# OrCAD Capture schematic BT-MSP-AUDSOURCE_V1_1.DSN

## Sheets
1 PAGE2 - MSP430: size B; title: BT-MSP-AUDSOURCE; rev: 1.1
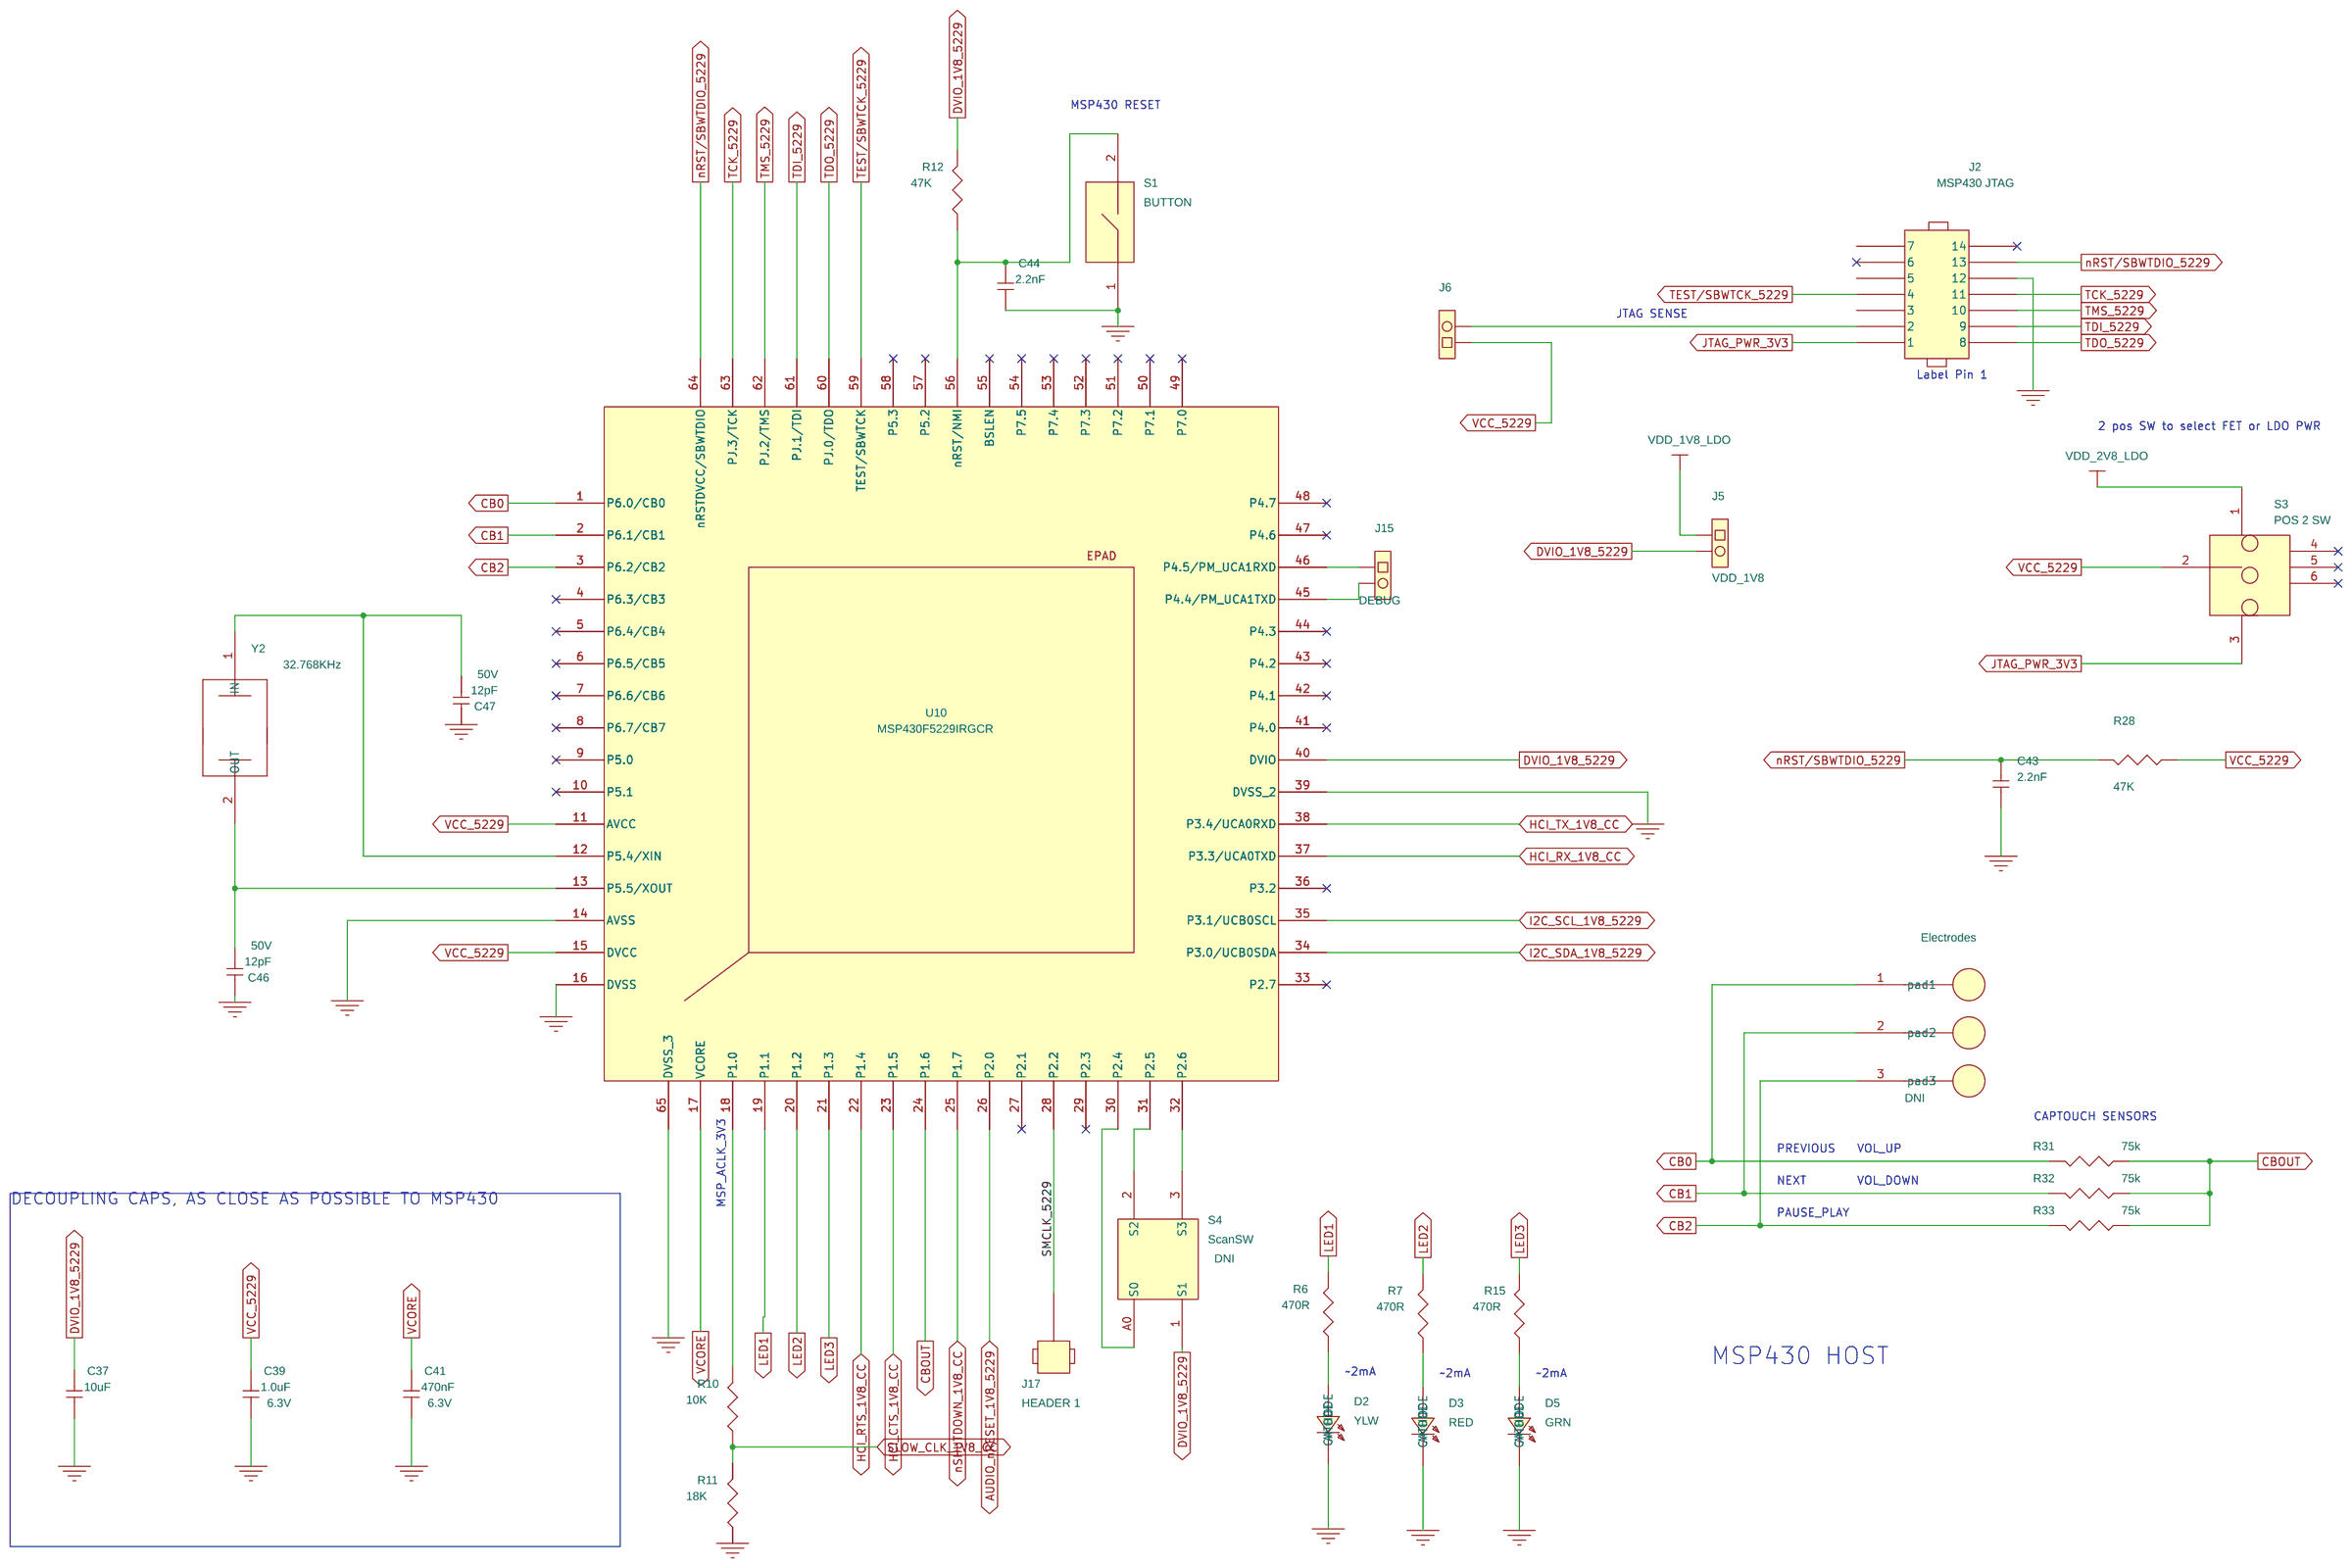
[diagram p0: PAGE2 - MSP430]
2 PAGE3 - CC256x QFN: size B
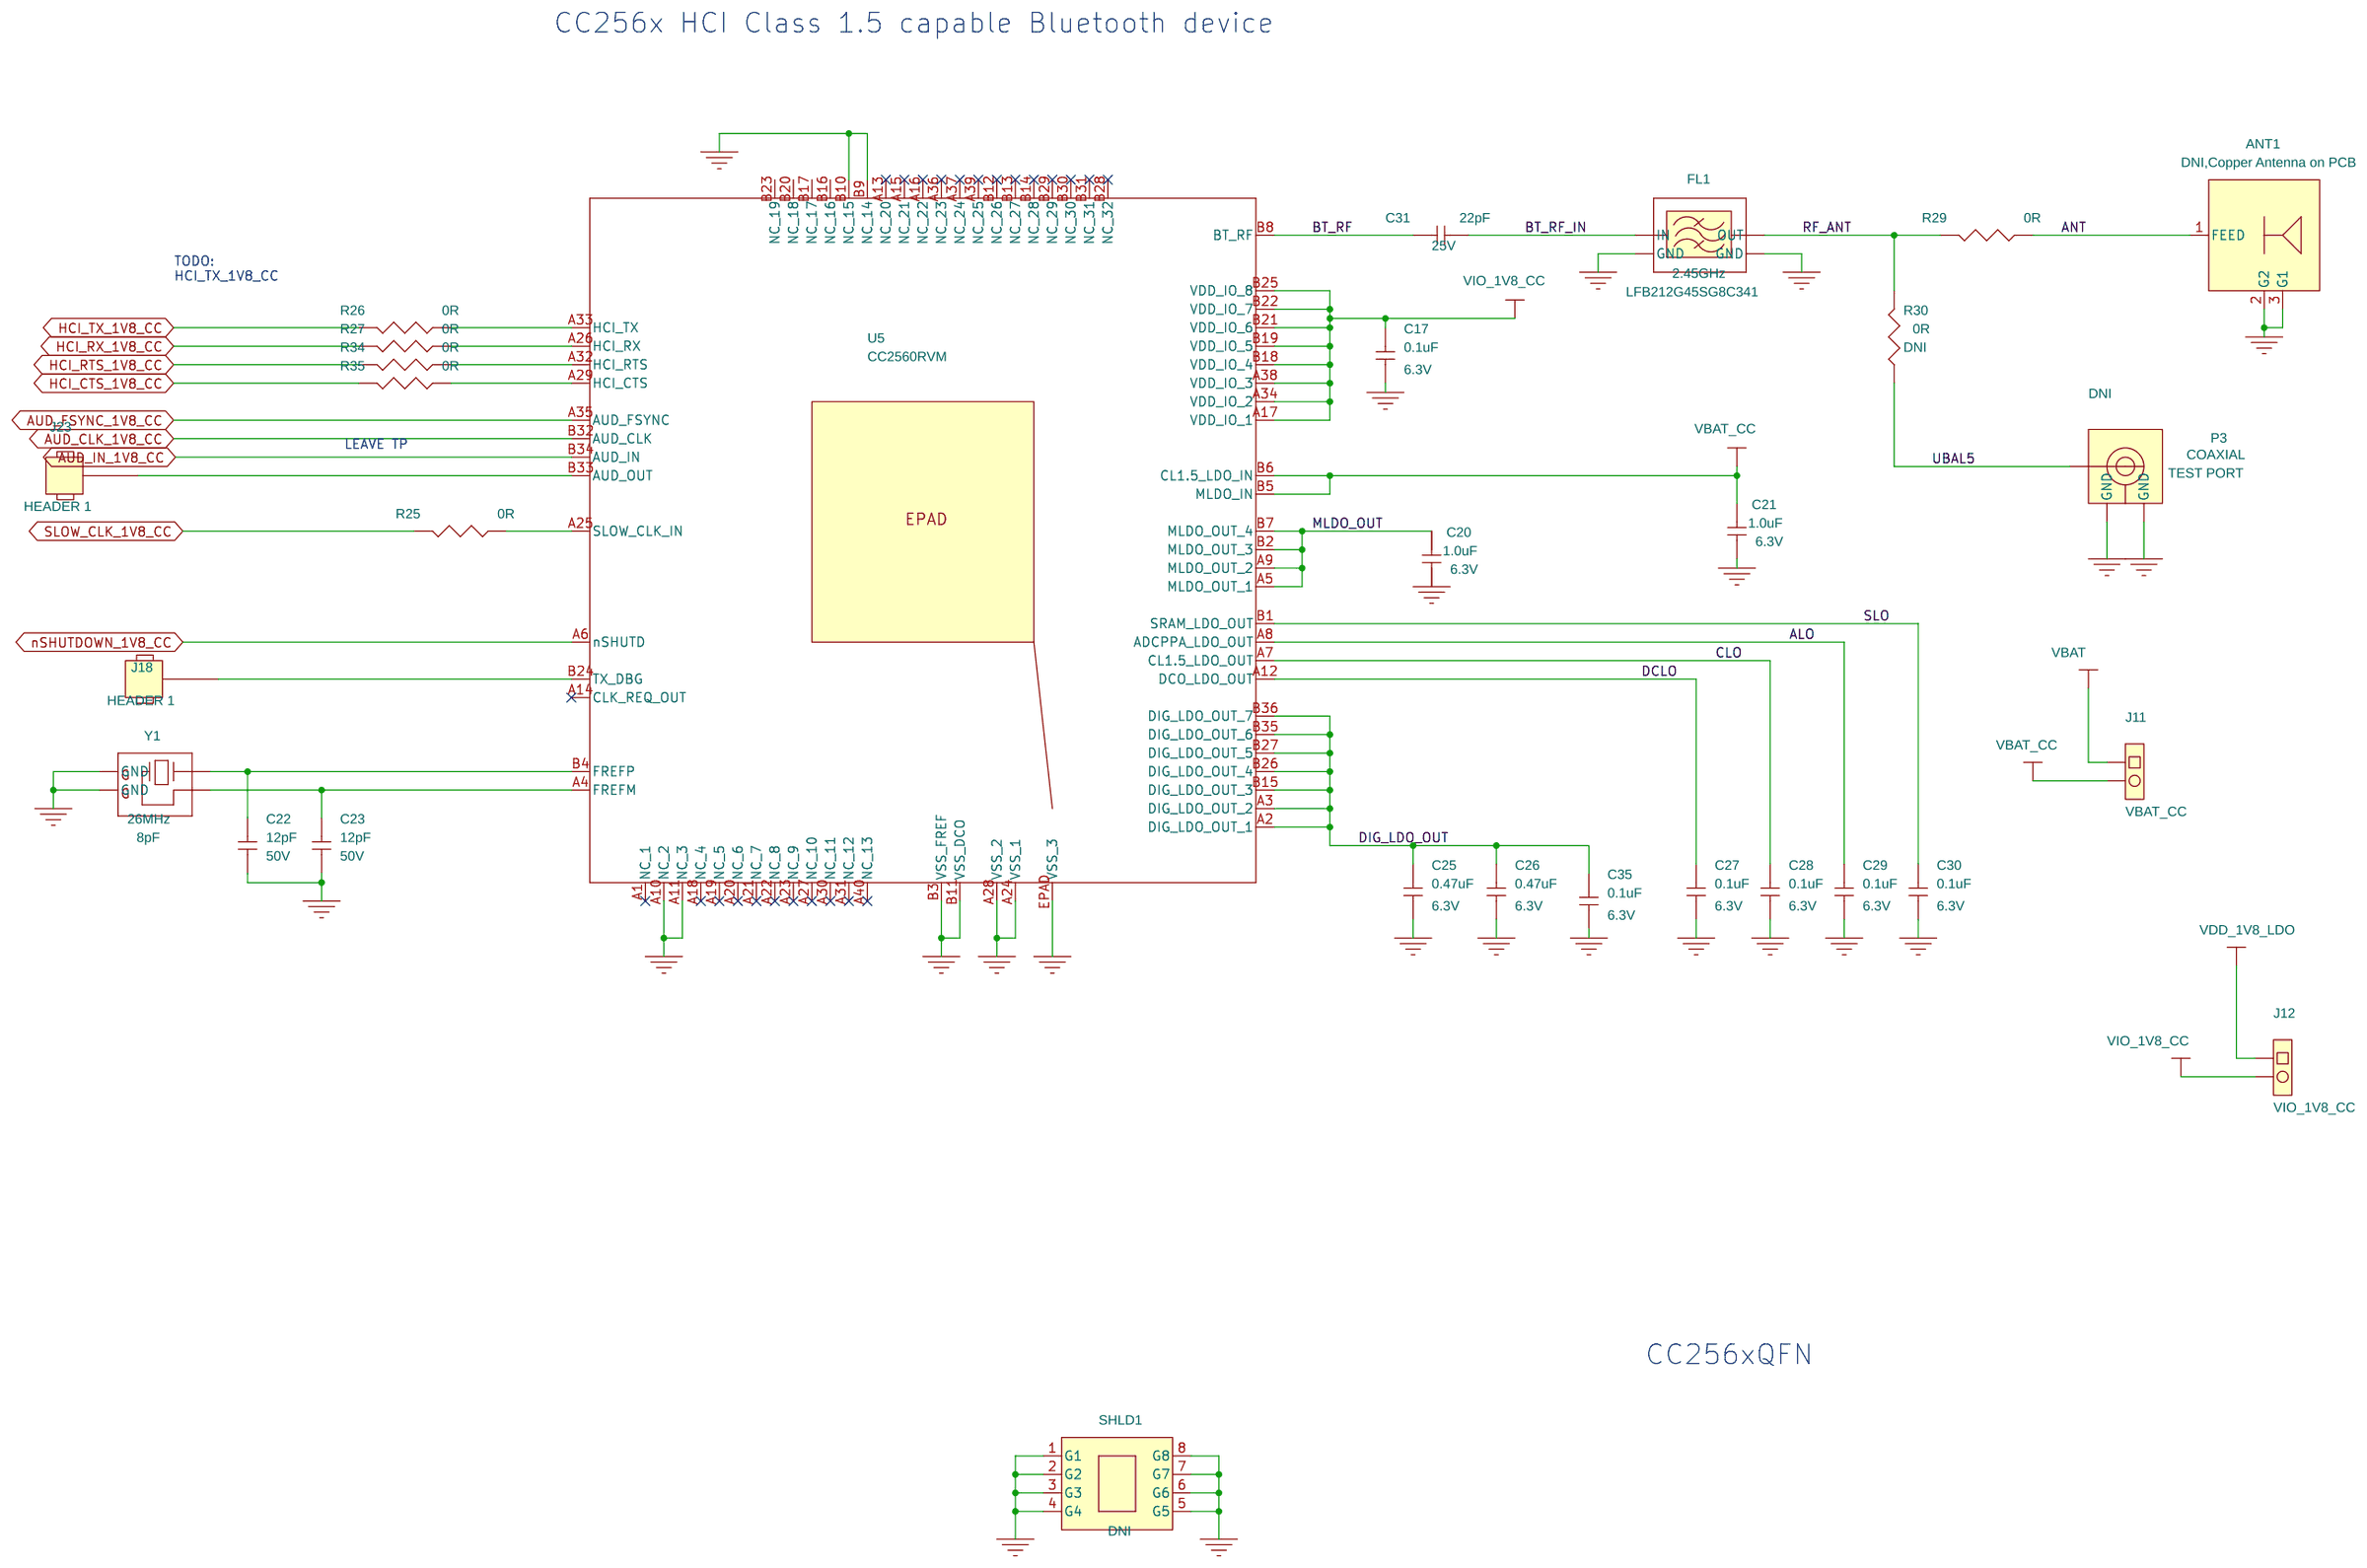
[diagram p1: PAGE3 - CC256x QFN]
3 PAGE4 - Power: size B
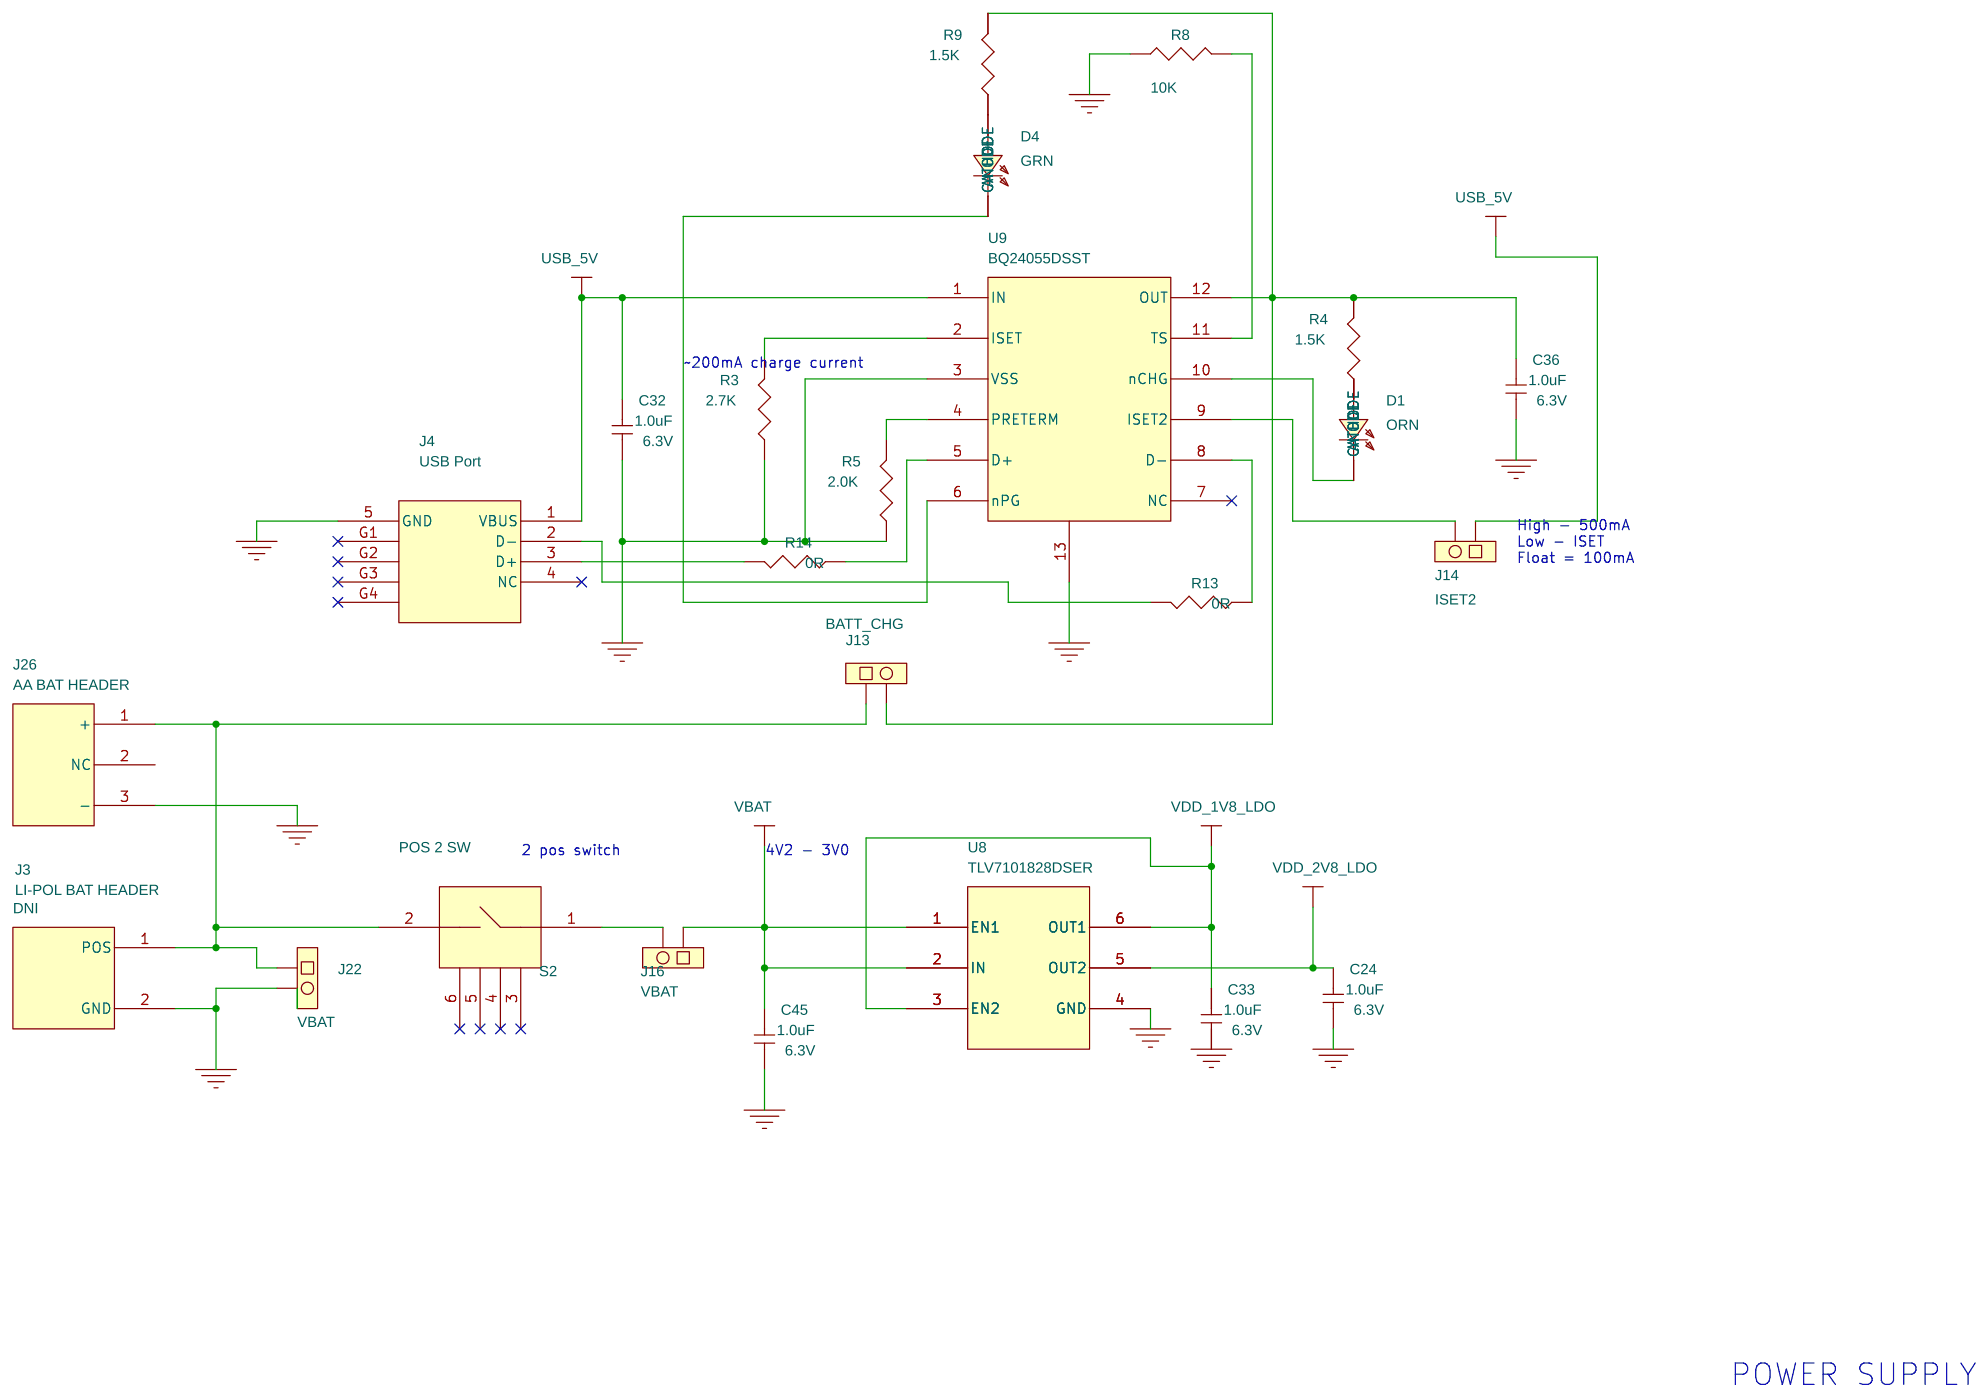
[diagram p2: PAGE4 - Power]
4 PAGE1 - Mic: size B
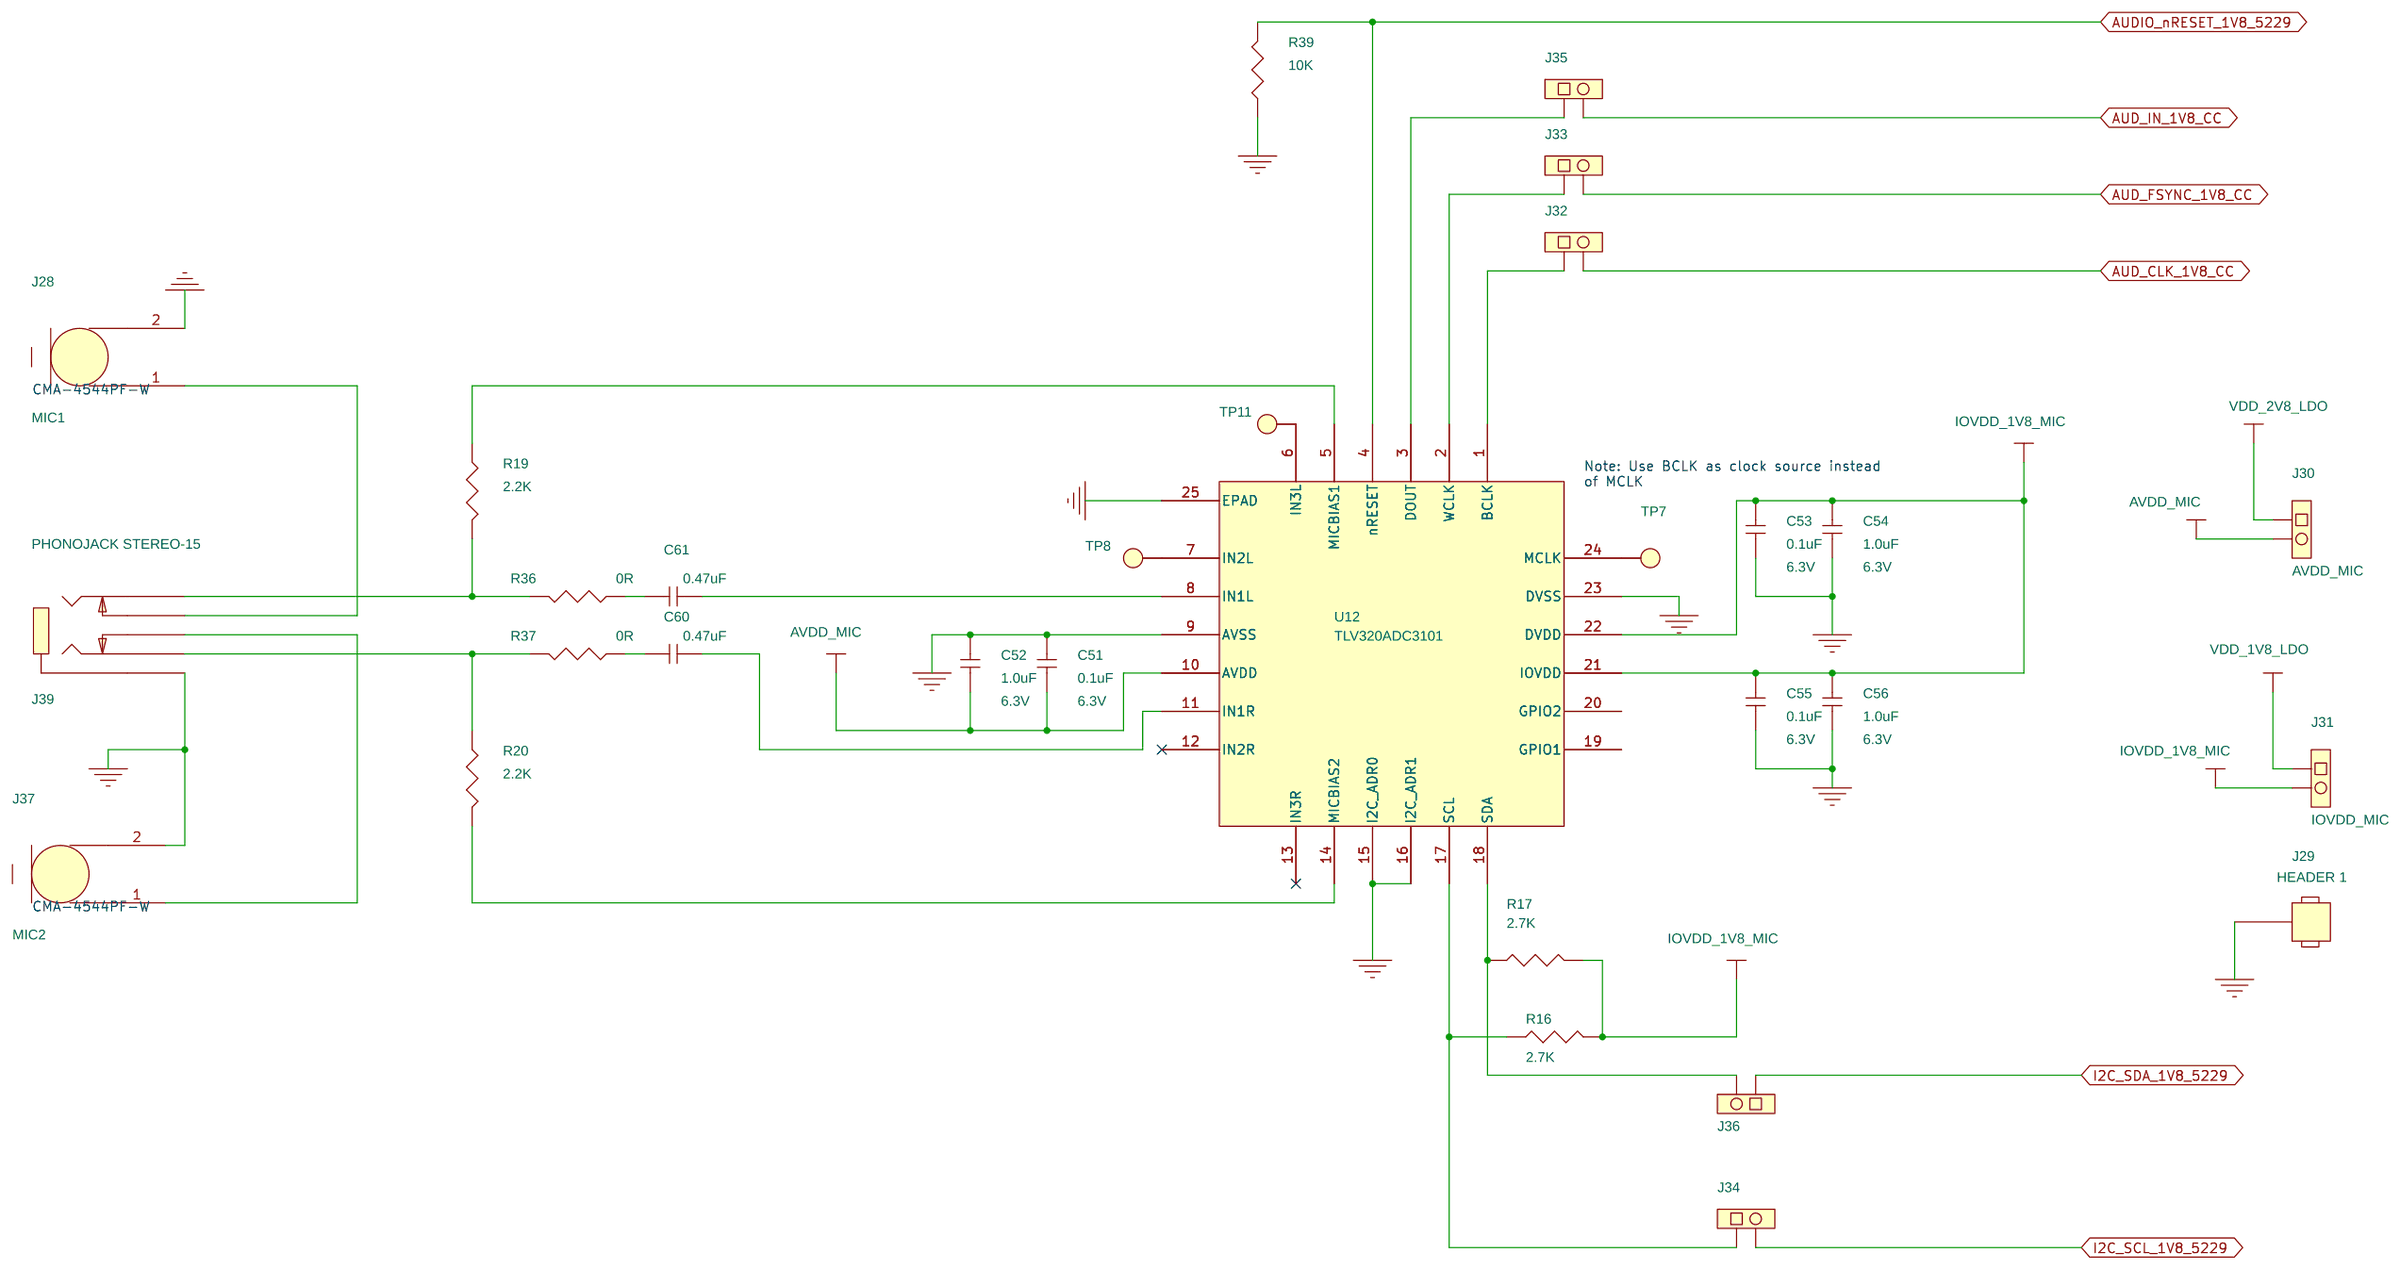
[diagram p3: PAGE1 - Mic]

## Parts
sheet PAGE1 - Mic
C51  0.1uF  [0402]
C52  1.0uF  [0402]
C53  0.1uF  [0402]
C54  1.0uF  [0402]
C55  0.1uF  [0402]
C56  1.0uF  [0402]
C60  0.47uF  [0402]
C61  0.47uF  [0402]
J28  MIC1  [MIC_THVT_cma-4544pf-w]
J29  HEADER 1  [TP101H50]
J30  1x2 THVT  [HDR_THVT_1X2_100_M]
J31  1x2 THVT  [HDR_THVT_1X2_100_M]
J32  1x2 THVT  [HDR_THVT_1X2_100_M]
J33  1x2 THVT  [HDR_THVT_1X2_100_M]
J34  1x2 THVT  [HDR_THVT_1X2_100_M]
J35  1x2 THVT  [HDR_THVT_1X2_100_M]
J36  1x2 THVT  [HDR_THVT_1X2_100_M]
J37  MIC2  [MIC_THVT_cma-4544pf-w]
J39  PHONOJACK STEREO-15  [jack_sm_sj1_3515]
R16  2.7K  [0402]
R17  2.7K  [0402]
R19  2.2K  [0402]
R20  2.2K  [0402]
R36  0R  [0402]
R37  0R  [0402]
R39  10K  [0402]
TP7  XX  [tp102]
TP8  XX  [tp102]
TP11  XX  [tp102]
U12  TLV320ADC3101  [QFN50P400X400X100-25N]
sheet PAGE2 - MSP430
C37  10uF  [0402]
C39  1.0uF  [0402]
C41  470nF  [0402]
C43  2.2nF  [0402]
C44  2.2nF  [0402]
C46  12pF  [0402]
C47  12pF  [0402]
D2  YLW  [LED_0603]
D3  RED  [LED_0603]
D5  GRN  [LED_0603]
J2  MSP430 JTAG  [te_5103308-2]
J5  1x2 THVT  [HDR_THVT_1X2_100_M]
J6  1x2 THVT  [HDR_THVT_1X2_100_M]
J15  1x2 THVT  [HDR_THVT_1X2_100_M]
J17  HEADER 1  [TP101H50]
R6  470R  [0402]
R7  470R  [0402]
R10  10K  [0402]
R11  18K  [0402]
R12  47K  [0402]
R15  470R  [0402]
R28  47K  [0402]
R31  75k  [0402]
R32  75k  [0402]
R33  75k  [0402]
S1  BUTTON  [sw_evq-11a05r]
S3  POS 2 SW  [SW_JS202011CQN]
S4  ScanSW  [SW_TPC1133G]
U10  MSP430F5229IRGCR  [QFN50P900X900X100-65NA]
U11  Electrodes  [3pelectrode]
Y2  32.768KHz  [XTAL_2_SM_130x63]
sheet PAGE3 - CC256x QFN
ANT1  2.4-2.5 GHz  [ANT_IIFA_CC2420_32MIL_MIR_1]
C17  0.1uF  [0402]
C20  1.0uF  [0402]
C21  1.0uF  [0402]
C22  12pF  [0402]
C23  12pF  [0402]
C25  0.47uF  [0402]
C26  0.47uF  [0402]
C27  0.1uF  [0402]
C28  0.1uF  [0402]
C29  0.1uF  [0402]
C30  0.1uF  [0402]
C31  22pF  [0201]
C35  0.1uF  [0402]
FL1  2.45GHz  [FIL_4_85x53x41]
J11  1x2 THVT  [HDR_THVT_1X2_100_M]
J12  1x2 THVT  [HDR_THVT_1X2_100_M]
J18  HEADER 1  [TP101H50]
J23  HEADER 1  [TP101H50]
P3  COAXIAL  [HRS_U-FL-R-SMT-1]
R25  0R  [0402]
R26  0R  [0402]
R27  0R  [0402]
R29  0R  [0402]
R30  0R  [0402]
R34  0R  [0402]
R35  0R  [0402]
SHLD1  RF SHIELD COVER  [SH_BMI-S-202_650x650]
U5  CC2560RVM  [PVQFN_RVM_EP134X122]
Y1  26MHz  [XTAL200X160X50]
sheet PAGE4 - Power
C24  1.0uF  [0402]
C32  1.0uF  [0402]
C33  1.0uF  [0402]
C36  1.0uF  [0402]
C45  1.0uF  [0402]
D1  ORN  [LED_0603]
D4  GRN  [LED_0603]
J3  LI-POL BAT HEADER  [JST_B2B-PH-K-S]
J4  USB Port  [JAE_DX2R005HN2]
J13  1x2 THVT  [HDR_THVT_1X2_100_M]
J14  1x2 THVT  [HDR_THVT_1X2_100_M]
J16  1x2 THVT  [HDR_THVT_1X2_100_M]
J22  1x2 THVT  [HDR_THVT_1X2_100_M]
J26  AA BAT HEADER  [MOLEX_22-03-5035]
R3  2.7K  [0402]
R4  1.5K  [0402]
R5  2.0K  [0402]
R8  10K  [0402]
R9  1.5K  [0402]
R13  0R  [0402]
R14  0R  [0402]
S2  POS 2 SW  [SW_JS202011CQN]
U8  TLV7101828DSER  [SON50P150X150X80-6]
U9  BQ24055DSST  [SON50P300X200X80-13]

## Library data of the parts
C17 C27-C30 C35 C51 C53 C55 = CAP_NP: ALT_SYMBOLS: 0402_SMALL; Link2MFG Datasheet: http://www.kemet.com/kemet/web/homepage/kechome.nsf/vapubfiles/F3102_X7R.pdf/$file/F3102_X7R.pdf; Manufacturer: Kemet; Manufacturer Part Number: C0402C104K9RACTU; Part Description: CAP CER 0.1UF 6.3V 10% X7R 0402; TEMP °C: -55 to 125; Unit price: 0.1; Voltage: 6.3V
C20 C21 C24 C32 C33 C36 C39 C45 C52 C54 C56 = CAP_NP: ALT_SYMBOLS: 0402_SMALL; Link2MFG Datasheet: http://search.digikey.com/scripts/DkSearch/dksus.dll?Detail&name=587-2594-2-ND; Manufacturer: Taiyo Yuden; Manufacturer Part Number: JMK105BJ105KV-F; Part Description: CAP CER 1.0UF 6.3V X5R 10% 0402; TEMP °C: -55 to 85; Unit price: 0.1; Voltage: 6.3V
C60 C61 = CAP_NP: ALT_SYMBOLS: 0402_SMALL; Link2MFG Datasheet: http://search.digikey.com/scripts/DkSearch/dksus.dll?Detail&name=587-2594-2-ND; Manufacturer: Taiyo Yuden; Manufacturer Part Number: JMK105BJ474KV-F; Part Description: CAP CER .47UF 6.3V X5R ±10% 0402; TEMP °C: -55 to 85; Unit price: 0.1; Voltage: 6.3V
J28 J37 = MIC_0: Manufacturer Part Number: CMA-4544PF-W; Part Description: MIC COND ANALOG OMNI -44DB
J29 = HEADER_1: Manufacturer Part Number: 5-146868-1; Part Description: CONN HEADER VERT .100" GOLD; Unit price: N/A
J30 = Header_1x2: Link2Local Datasheet: C:\PCB_LIBRARY\CADENCE\DATASHEETS\HMTSW_SERIES; Link2MFG Datasheet: http://www.samtec.com/ProductInformation/TechnicalSpecifications/Overview.aspx?series=HMTSW; Manufacturer: Samtec; Manufacturer Part Number: 3-644456-2; Part Description: CONN HEADER VERT 2POS .100 TIN; TEMP °C: -55 TO 125; TI_SILKTEXT: AVDD_MIC; Unit price: 0.43
J31 = Header_1x2: Link2Local Datasheet: C:\PCB_LIBRARY\CADENCE\DATASHEETS\HMTSW_SERIES; Link2MFG Datasheet: http://www.samtec.com/ProductInformation/TechnicalSpecifications/Overview.aspx?series=HMTSW; Manufacturer: Samtec; Manufacturer Part Number: 3-644456-2; Part Description: CONN HEADER VERT 2POS .100 TIN; TEMP °C: -55 TO 125; TI_SILKTEXT: IOVDD_MIC; Unit price: 0.43
J32-J36 = Header_1x2: Link2Local Datasheet: C:\PCB_LIBRARY\CADENCE\DATASHEETS\HMTSW_SERIES; Link2MFG Datasheet: http://www.samtec.com/ProductInformation/TechnicalSpecifications/Overview.aspx?series=HMTSW; Manufacturer: Samtec; Manufacturer Part Number: 3-644456-2; Part Description: CONN HEADER VERT 2POS .100 TIN; TEMP °C: -55 TO 125; TI_SILKTEXT: SVDD; Unit price: 0.43
J39 = PHONOJACK_STEREO-15: Manufacturer Part Number: SJ1-3515-SMT-TR; Part Description: CONN JACK STEREO 5POS 3.5MM SMD
R3 R16 R17 = RESISTOR: ALT_SYMBOLS: 0402_SMALL; Link2Local Datasheet: C:\PCB_LIBRARY\CADENCE\DATASHEETS\AOA0000PE3.pdf; Link2MFG Datasheet: http://industrial.panasonic.com/www-data/pdf/AOA0000/AOA0000PE3.pdf; Manufacturer: Panasonic - ECG; Manufacturer Part Number: ERJ-2GEJ272X; Part Description: RES 2.7K OHM 1/10W 5% 0402 SMD; TEMP °C: ±100ppm/°C; Unit price: 0.1; Watt: 1/10W
R19 R20 = RESISTOR: ALT_SYMBOLS: 0402_SMALL; Link2Local Datasheet: C:\PCB_LIBRARY\CADENCE\DATASHEETS\AOA0000PE3.pdf; Link2MFG Datasheet: http://industrial.panasonic.com/www-data/pdf/AOA0000/AOA0000PE3.pdf; Manufacturer: Panasonic - ECG; Manufacturer Part Number: ERJ-2GEJ222X; Part Description: RES 2.2K OHM 1/10W 5% 0402 SMD; TEMP °C: ±100ppm/°C; Unit price: 0.1; Watt: 1/10W
R25-R27 R29 R34-R37 = RESISTOR: ALT_SYMBOLS: 0402_SMALL; Link2MFG Datasheet: http://search.digikey.com/scripts/DkSearch/dksus.dll?Detail&name=P0.0JTR-ND; Manufacturer: Panasonic - ECG; Manufacturer Part Number: ERJ-2GE0R00X; Part Description: RES 0.0 OHM 1/10W JUMP 0402 SMD; TEMP °C: -100/+600ppm/°C; Unit price: 0.05; Watt: 1/10W
R8 R10 R39 = RESISTOR: ALT_SYMBOLS: 0402_SMALL; Link2Local Datasheet: C:\PCB_LIBRARY\CADENCE\DATASHEETS\AOA0000PE3.pdf; Link2MFG Datasheet: http://industrial.panasonic.com/www-data/pdf/AOA0000/AOA0000PE3.pdf; Manufacturer: Panasonic - ECG; Manufacturer Part Number: ERJ-2RKF1002X; Part Description: RES 10.0K OHM 1/10W 1% 0402 SMD; TEMP °C: ±100ppm/°C; Unit price: 0.1; Watt: 1/10W
TP7 TP8 TP11 = TESTPOINT: Note: NO PART.  TEST PAD ONLY; Part Description: TP_VIA_030RND020; Unit price: N/A
U12 = TLV320ADC3101_0
C37 = CAP_NP: ALT_SYMBOLS: 0402_SMALL; Link2MFG Datasheet: http://search.digikey.com/scripts/DkSearch/dksus.dll?Detail&name=587-2594-2-ND; Manufacturer: TDK Corporation; Manufacturer Part Number: C1005X5R0G106M050BB; Part Description: CAP CER 10UF 4V 20% X5R 0402; TEMP °C: -55 to 85; Unit price: 0.1; Voltage: 6.3V
C41 = CAP_NP: ALT_SYMBOLS: 0402_SMALL; Link2MFG Datasheet: http://search.digikey.com/scripts/DkSearch/dksus.dll?Detail&name=587-2594-2-ND; Manufacturer: Taiyo Yuden; Manufacturer Part Number: JMK105BJ474KV-F; Part Description: CAP CER 0.47UF 6.3V 10% X5R 0402; TEMP °C: -55 to 85; Unit price: 0.1; Voltage: 6.3V
C43 = CAP_NP: ALT_SYMBOLS: 0402_SMALL; Link2Local Datasheet: C:\PCB_LIBRARY\CADENCE\DATASHEETS\dlmk_e.pdf; Link2MFG Datasheet: http://www.yuden.co.jp/ut/product/pdf/dlmk_e.pdf; Manufacturer: Taiyo Yuden; Manufacturer Part Number: C1005X7R1H222K050BA; Part Description: CAP CER 2200PF 50V 10% X7R 0402; TEMP °C: -55 to 85; Unit price: 0.1; Voltage: 6.3V
C44 = CAP_NP: ALT_SYMBOLS: 0402_SMALL; Link2MFG Datasheet: http://search.digikey.com/scripts/DkSearch/dksus.dll?Detail&name=587-2594-2-ND; Manufacturer: Taiyo Yuden; Manufacturer Part Number: C1005X7R1H222K050BA; Part Description: CAP CER 2200PF 50V 10% X7R 0402; TEMP °C: -55 to 85; Unit price: 0.1; Voltage: 6.3V
C46 C47 = CAP_NP: ALT_SYMBOLS: 0402_SMALL; Link2MFG Datasheet: http://search.digikey.com/scripts/DkSearch/dksus.dll?Detail&name=587-2594-2-ND; Manufacturer: Taiyo Yuden; Manufacturer Part Number: CGA2B2C0G1H120J050BA; Part Description: CAP CER 12PF 50V 5% NP0 0402; TEMP °C: -55 to 85; Unit price: 0.1; Voltage: 50V
D2 = LED_2P: Link2Local Datasheet: C:\PCB_LIBRARY\CADENCE\DATASHEETS\LNJ208R8ARA_BEK.pdf; Link2MFG Datasheet: http://www.semicon.panasonic.co.jp/ds4/LNJ208R8ARA_BEK.pdf; Manufacturer: OSRAM Opto Semiconductors Inc; Manufacturer Part Number: LY L29K-H1K2-26-Z; Part Description: LED YELLOW 587NM 0603 SMD; TI_SILKTEXT: 1V8 PWR; Unit price: 0.22; Voltage: 1.72V
D3 = LED_2P: Link2Local Datasheet: C:\PCB_LIBRARY\CADENCE\DATASHEETS\LNJ208R8ARA_BEK.pdf; Link2MFG Datasheet: http://www.semicon.panasonic.co.jp/ds4/LNJ208R8ARA_BEK.pdf; Manufacturer: OSRAM Opto Semiconductors Inc; Manufacturer Part Number: LS L29K-H1J2-1-Z; Part Description: LED SMARTLED RED 630NM 0603 SMD; TI_SILKTEXT: 1V8 PWR; Unit price: 0.22; Voltage: 1.72V
D4 D5 = LED_2P: Link2Local Datasheet: C:\PCB_LIBRARY\CADENCE\DATASHEETS\LNJ208R8ARA_BEK.pdf; Link2MFG Datasheet: http://www.semicon.panasonic.co.jp/ds4/LNJ208R8ARA_BEK.pdf; Manufacturer: OSRAM Opto Semiconductors Inc; Manufacturer Part Number: LG L29K-G2J1-24-Z; Part Description: LED SMARTLED GREEN 570NM 0603; TI_SILKTEXT: 1V8 PWR; Unit price: 0.22; Voltage: 1.72V
J2 = CONN_PCB_7x2: Manufacturer Part Number: 5103308-2; Unit price: 1.39
J5 J6 = Header_1x2: Link2Local Datasheet: C:\PCB_LIBRARY\CADENCE\DATASHEETS\HMTSW_SERIES; Link2MFG Datasheet: http://www.samtec.com/ProductInformation/TechnicalSpecifications/Overview.aspx?series=HMTSW; Manufacturer: Samtec; Manufacturer Part Number: 3-644456-2; Part Description: CONN HEADER VERT 2POS .100 TIN; TEMP °C: -55 TO 125; TI_SILKTEXT: VDD_1V8; Unit price: 0.43(no stock)
J15 = Header_1x2: Link2Local Datasheet: C:\PCB_LIBRARY\CADENCE\DATASHEETS\HMTSW_SERIES; Link2MFG Datasheet: http://www.samtec.com/ProductInformation/TechnicalSpecifications/Overview.aspx?series=HMTSW; Manufacturer: Samtec; Manufacturer Part Number: 3-644456-2; Part Description: CONN HEADER VERT 2POS .100 TIN; TEMP °C: -55 TO 125; TI_SILKTEXT: DEBUG; Unit price: 0.43(no stock)
J17 J18 J23 = HEADER_1: Manufacturer Part Number: 5-146868-1; NOTE: DNI; Part Description: CONN HEADER VERT .100" GOLD; Unit price: N/A
R6 R7 R15 = RESISTOR: ALT_SYMBOLS: 0402_SMALL; Link2Local Datasheet: C:\PCB_LIBRARY\CADENCE\DATASHEETS\AOA0000PE3.pdf; Link2MFG Datasheet: http://industrial.panasonic.com/www-data/pdf/AOA0000/AOA0000PE3.pdf; Manufacturer: Panasonic - ECG; Manufacturer Part Number: ERJ-2GEJ471X; Part Description: RES 470 OHM 1/10W 5% 0402 SMD; TEMP °C: ±100ppm/°C; Unit price: 0.1; Watt: 1/10W
R11 = RESISTOR: ALT_SYMBOLS: 0402_SMALL; Link2Local Datasheet: C:\PCB_LIBRARY\CADENCE\DATASHEETS\AOA0000PE3.pdf; Link2MFG Datasheet: http://industrial.panasonic.com/www-data/pdf/AOA0000/AOA0000PE3.pdf; Manufacturer: Panasonic - ECG; Manufacturer Part Number: ERJ-2GEJ183X; Part Description: RES 18K OHM 1/10W 5% 0402 SMD; TEMP °C: ±100ppm/°C; Unit price: 0.1; Watt: 1/10W
R12 = RESISTOR: ALT_SYMBOLS: 0402_SMALL; Link2Local Datasheet: C:\PCB_LIBRARY\CADENCE\DATASHEETS\AOA0000PE3.pdf; Link2MFG Datasheet: http://industrial.panasonic.com/www-data/pdf/AOA0000/AOA0000PE3.pdf; Manufacturer: Panasonic - ECG; Manufacturer Part Number: ERJ-2GEJ473X; Part Description: RES 47K OHM 1/10W 5% 0402 SMD; TEMP °C: ±100ppm/°C; Unit price: 0.1; Watt: 1/10W
R28 = RESISTOR: ALT_SYMBOLS: 0402_SMALL; Link2MFG Datasheet: http://search.digikey.com/scripts/DkSearch/dksus.dll?Detail&name=P0.0JTR-ND; Manufacturer: Panasonic - ECG; Manufacturer Part Number: ERJ-2GEJ473X; Part Description: RES 47K OHM 1/10W 5% 0402 SMD; TEMP °C: -100/+600ppm/°C; Unit price: 0.05; Watt: 1/10W
R31-R33 = RESISTOR: ALT_SYMBOLS: 0402_SMALL; Link2MFG Datasheet: http://search.digikey.com/scripts/DkSearch/dksus.dll?Detail&name=P0.0JTR-ND; Manufacturer: Panasonic - ECG; Manufacturer Part Number: ERJ-2GEJ753X; Part Description: RES 75K OHM 1/10W 5% 0402 SMD; TEMP °C: -100/+600ppm/°C; Unit price: 0.05; Watt: 1/10W
S1 = BUTTON: Manufacturer Part Number: EVQ-11A05R; Part Description: MSP430 Reset Button; Unit price: 0.29
S3 = Switch_0: Manufacturer Part Number: JS202011CQN; Part Description: SW SLIDE DPDT 6VDC 0.3A PCMNT; Unit price: 0.39
S4 = ScanSW_1: Note: DNI; Part Description: Scan Switch; Unit price: 2.15
U10 = MSP430F5229IRGC_1: Manufacturer: Texas Instruments; Part Description: Mixed Signal Microcontroller; Unit price: 2.65
U11 = Electrodes: Note: DNI; Unit price: N/A
Y2 = 32_12.768KHz: Manufacturer: Abracon Corporation; Manufacturer Part Number: ABS07-32.768KHZ-T; Part Description: CRYSTAL 32.768KHZ 12.5PF SMD; Unit price: 1.18
ANT1 = ANT_IIFA_CC2420_32mil_MIR: NOTE: DNI,Copper Antenna on PCB; Part Description: PCB ANTENNA; Unit price: N/A
C22 C23 = CAP_NP: ALT_SYMBOLS: 0402_SMALL; Link2Local Datasheet: C:\PCB_LIBRARY\CADENCE\DATASHEETS\GRM1555C1H100JZ01.pdf; Link2MFG Datasheet: http://search.digikey.com/scripts/DkSearch/dksus.dll?Detail&name=490-1278-2-ND; Manufacturer: Murata Electronics; Manufacturer Part Number: CGA2B2C0G1H120J050BA; Part Description: CAP CER 12PF 50V 5% NP0 0402; TEMP °C: -55 to 125; Unit price: 0.1; Voltage: 50V
C25 C26 = CAP_NP: ALT_SYMBOLS: 0402_SMALL; Link2Local Datasheet: C:\PCB_LIBRARY\CADENCE\DATASHEETS\dlmk_e.pdf; Link2MFG Datasheet: http://www.yuden.co.jp/ut/product/pdf/dlmk_e.pdf; Manufacturer: Taiyo Yuden; Manufacturer Part Number: JMK105BJ474KV-F; Part Description: CAP CER .47UF 6.3V X5R ±10% 0402; TEMP °C: -55 to 85; Unit price: 0.1; Voltage: 6.3V
C31 = CAP_NP: ALT_SYMBOLS: 0201_small; Link2MFG Datasheet: http://search.digikey.com/us/en/products/GRM0335C1E1R8CD01D/490-1244-2-ND/587245; Manufacturer: Murata Electronics North America; Manufacturer Part Number: GRM0335C1E220JD01D; Part Description: CAP CER 22PF 25V 5% NP0 0201; TEMP °C: -55 to 125; Unit price: tbd; Voltage: 25V
FL1 = FILTER_4PIN_GND: Link2Local Datasheet: C:\PCB_LIBRARY\CADENCE\DATASHEETS\Search Engine  Murata Manufacturing; Link2MFG Datasheet: http://search.murata.co.jp/Ceramy/CatalogAction.do?sHinnm=?%C2%A0&sNHinnm=LFB212G45SG8A127&sNhin_key=LFB212G45SG8A127&sLang=en; Manufacturer: Murata Electronics; Manufacturer Part Number: LFB212G45SG8C341; Note: PLACE BROWN MARKING UP, Contact Murata for Part; Part Description: FILTER CER BAND PASS 2.45GHZ SMD; Unit price: 0.36
J11 = Header_1x2: Link2Local Datasheet: C:\PCB_LIBRARY\CADENCE\DATASHEETS\HMTSW_SERIES; Link2MFG Datasheet: http://www.samtec.com/ProductInformation/TechnicalSpecifications/Overview.aspx?series=HMTSW; Manufacturer: Samtec; Manufacturer Part Number: 3-644456-2; Part Description: CONN HEADER VERT 2POS .100 TIN; TEMP °C: -55 TO 125; TI_SILKTEXT: VBAT_CC; Unit price: 0.43(no stock)
J12 = Header_1x2: Link2Local Datasheet: C:\PCB_LIBRARY\CADENCE\DATASHEETS\HMTSW_SERIES; Link2MFG Datasheet: http://www.samtec.com/ProductInformation/TechnicalSpecifications/Overview.aspx?series=HMTSW; Manufacturer: Samtec; Manufacturer Part Number: 3-644456-2; Part Description: CONN HEADER VERT 2POS .100 TIN; TEMP °C: -55 TO 125; TI_SILKTEXT: VIO_1V8_CC; Unit price: 0.43(no stock)
P3 = CON_COAXIAL_UFL-R-SMT_0: Note: DNI; Part Description: RECEPTACLE_CON_COAXIAL_UFL-R-SMT; TI_SILKTEXT: TEST PORT; Unit price: 1.67
R30 = RESISTOR: ALT_SYMBOLS: 0402_SMALL; Link2MFG Datasheet: http://search.digikey.com/scripts/DkSearch/dksus.dll?Detail&name=P0.0JTR-ND; Manufacturer: Panasonic - ECG; Manufacturer Part Number: ERJ-2GE0R00X; Note: DNI; Part Description: RES 0.0 OHM 1/10W JUMP 0402 SMD; TEMP °C: -100/+600ppm/°C; Unit price: 0.05; Watt: 1/10W
SHLD1 = RF_SHIELD_8P: Manufacturer: Laird Technologies EMI; Manufacturer Part Number: BMI-S-202-F; Note: DNI; Part Description: BOARD SHIELD .65X.65" FRAME; Unit price: 0.73
U5 = BL6450Q_RVM: Link2Local Datasheet: C:\PCB_LIBRARY\CADENCE\DATASHEETS\SWRS115A_BL6450Q_ProductPreview.pdf; Link2MFG Datasheet: DRAFT ONLY; Manufacturer: Texas Instruments; Manufacturer Part Number: CC2560ARVMR; Part Description: Bluetooth BR/EDR/LE and ANT Single-Chip Solution; Unit price: 1.86
Y1 = XTAL_4P_GND: Link2Local Datasheet: C:\PCB_LIBRARY\CADENCE\DATASHEETS\FA-128_E107.pdf; Link2MFG Datasheet: http://ndap3-net.ebz.epson.co.jp/w/www/PDFS/epdoc_qd.nsf/85a4e2c523a1f89349257068002f9e30/255cb2884010a1f9492571f0004c7d72/$FI; Load Cap: 8pF; Manufacturer: NDK; Manufacturer Part Number: NX2016SA (EXS00A-CS06025); Part Description: CRYSTAL 26MHz; TEMP °C: -20 to 70; Unit price: 2.1
D1 = LED_2P: Link2Local Datasheet: C:\PCB_LIBRARY\CADENCE\DATASHEETS\LNJ208R8ARA_BEK.pdf; Link2MFG Datasheet: http://www.semicon.panasonic.co.jp/ds4/LNJ208R8ARA_BEK.pdf; Manufacturer: OSRAM Opto Semiconductors Inc; Manufacturer Part Number: LO L29K-J2L1-24-Z; Part Description: LED ORANGE 606NM 0603 SMD; TI_SILKTEXT: 1V8 PWR; Unit price: 0.22; Voltage: 1.72V
J3 = BATTERY: Manufacturer Part Number: 455-1704-ND; Note: DNI; Part Description: li-ion battery header standard jst-ph; Unit price: 0.16
J4 = USB_Port_3: Manufacturer Part Number: DX2R005HN2E700; Unit price: 1.27
J13 = Header_1x2: Link2Local Datasheet: C:\PCB_LIBRARY\CADENCE\DATASHEETS\HMTSW_SERIES; Link2MFG Datasheet: http://www.samtec.com/ProductInformation/TechnicalSpecifications/Overview.aspx?series=HMTSW; Manufacturer: Samtec; Manufacturer Part Number: 3-644456-2; Part Description: CONN HEADER VERT 2POS .100 TIN; TEMP °C: -55 TO 125; TI_SILKTEXT: BATT_CHG; Unit price: 0.43(no stock)
J14 = Header_1x2: Link2Local Datasheet: C:\PCB_LIBRARY\CADENCE\DATASHEETS\HMTSW_SERIES; Link2MFG Datasheet: http://www.samtec.com/ProductInformation/TechnicalSpecifications/Overview.aspx?series=HMTSW; Manufacturer: Samtec; Manufacturer Part Number: 3-644456-2; Part Description: CONN HEADER VERT 2POS .100 TIN; TEMP °C: -55 TO 125; TI_SILKTEXT: ISET2; Unit price: 0.43(no stock)
J16 J22 = Header_1x2: Link2Local Datasheet: C:\PCB_LIBRARY\CADENCE\DATASHEETS\HMTSW_SERIES; Link2MFG Datasheet: http://www.samtec.com/ProductInformation/TechnicalSpecifications/Overview.aspx?series=HMTSW; Manufacturer: Samtec; Manufacturer Part Number: 3-644456-2; Part Description: CONN HEADER VERT 2POS .100 TIN; TEMP °C: -55 TO 125; TI_SILKTEXT: VBAT; Unit price: 0.43(no stock)
J26 = AA_BAT_HEADER: Manufacturer Part Number: 0022035035; Part Description: Battery Connector; Unit price: 0.53
R4 R9 = RESISTOR: ALT_SYMBOLS: 0402_SMALL; Link2Local Datasheet: C:\PCB_LIBRARY\CADENCE\DATASHEETS\AOA0000PE3.pdf; Link2MFG Datasheet: http://industrial.panasonic.com/www-data/pdf/AOA0000/AOA0000PE3.pdf; Manufacturer: Panasonic - ECG; Manufacturer Part Number: ERJ-2GEJ152X; Part Description: RES 1.5K OHM 1/10W 5% 0402 SMD; TEMP °C: ±100ppm/°C; Unit price: 0.1; Watt: 1/10W
R5 = RESISTOR: ALT_SYMBOLS: 0402_SMALL; Link2Local Datasheet: C:\PCB_LIBRARY\CADENCE\DATASHEETS\AOA0000PE3.pdf; Link2MFG Datasheet: http://industrial.panasonic.com/www-data/pdf/AOA0000/AOA0000PE3.pdf; Manufacturer: Panasonic - ECG; Manufacturer Part Number: ERJ-2GEJ202X; Part Description: RES 2K OHM 1/10W 5% 0402 SMD; TEMP °C: ±100ppm/°C; Unit price: 0.1; Watt: 1/10W
R13 R14 = RESISTOR: ALT_SYMBOLS: 0402_SMALL; Link2Local Datasheet: C:\PCB_LIBRARY\CADENCE\DATASHEETS\AOA0000PE3.pdf; Link2MFG Datasheet: http://industrial.panasonic.com/www-data/pdf/AOA0000/AOA0000PE3.pdf; Manufacturer: Panasonic - ECG; Manufacturer Part Number: ERJ-2GE0R00X; Part Description: RES 0.0 OHM 1/10W JUMP 0402 SMD; TEMP °C: ±100ppm/°C; Unit price: 0.1; Watt: 1/10W
S2 = BUTTON_3: Manufacturer Part Number: JS202011CQN; Part Description: SW SLIDE DPDT 6VDC 0.3A PCMNT; Unit price: 0.39
U8 = TLV7101828_0: Unit price: 0.19
U9 = bq24055_1: Manufacturer: Texas Instruments; Part Description: Single Cell Li-Ion Battery Charger; Unit price: 0.6

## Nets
AVDD_MIC: C51.2 C52.2 J30.2 U12.10(AVDD)
GND: ANT1.2(G2) ANT1.3(G1) C17.2 C20.2 C21.2 C22.1 C23.1 C24.2 C25.2 C26.2 C27.2 C28.2 C29.2 C30.2 C32.2 C33.2 C35.2 C36.2 C37.2 C39.2 C41.2 C43.2 C44.2 C45.2 C46.1 C47.1 C51.1 C52.1 C53.2 C54.2 C55.2 C56.2 D2.2(CATHODE) D3.2(CATHODE) D5.2(CATHODE) FL1.1(GND) FL1.3(GND) J2.9(12) J3.2(GND) J4.5(GND) J22.2 J26.3(-) J28.2 J29.1 J37.2 J39.1 P3.2A(GND) P3.2B(GND) R3.2 R5.2 R8.2 R11.2 R39.2 S1.1 SHLD1.1(G1) SHLD1.2(G2) SHLD1.3(G3) SHLD1.4(G4) SHLD1.5(G5) SHLD1.6(G6) SHLD1.7(G7) SHLD1.8(G8) U5.A10(NC_2) U5.A11(NC_3) U5.A24(VSS_1) U5.A28(VSS_2) U5.B3(VSS_FREF) U5.B9(NC_14) U5.B10(NC_15) U5.B11(VSS_DCO) U5.EPAD(VSS_3) U8.4(GND) U9.3(VSS) U9.13 U10.14(AVSS) U10.16(DVSS) U10.39(DVSS_2) U10.65(DVSS_3) U12.9(AVSS) U12.15(I2C_ADR0) U12.16(I2C_ADR1) U12.23(DVSS) U12.25(EPAD) Y1.2(GND) Y1.4(GND)
VBAT: C45.1 J11.1 J16.1 U8.1(EN1) U8.2(IN)
VBAT_CC: C21.1 J11.2 U5.B5(MLDO_IN) U5.B6(CL1.5_LDO_IN)
VCC_5229: C39.1 J6.1 R28.1 S3.2 U10.11(AVCC) U10.15(DVCC)
VDD_1V8_LDO: C33.1 J5.1 J12.1 J31.1 U8.3(EN2) U8.6(OUT1)
VDD_2V8_LDO: C24.1 J30.1 S3.1 U8.5(OUT2)
ALO: C29.1 U5.A8(ADCPPA_LDO_OUT)
ANT: ANT1.1(FEED) R29.1
AUD_CLK_1V8_CC: J32.2 U5.B32(AUD_CLK)
AUD_FSYNC_1V8_CC: J33.2 U5.A35(AUD_FSYNC)
AUD_IN_1V8_CC: J35.2 U5.B34(AUD_IN)
AUDIO_nRESET_1V8_5229: R39.1 U10.26(P2.0) U12.4(nRESET)
BT_RF: C31.1 U5.B8(BT_RF)
BT_RF_IN: C31.2 FL1.4(IN)
CB0: R31.2 U10.1(P6.0/CB0) U11.1(pad1)
CB1: R32.2 U10.2(P6.1/CB1) U11.2(pad2)
CB2: R33.2 U10.3(P6.2/CB2) U11.3(pad3)
CBOUT: R31.1 R32.1 R33.1 U10.24(P1.6)
CLO: C28.1 U5.A7(CL1.5_LDO_OUT)
DCLO: C27.1 U5.A12(DCO_LDO_OUT)
DIG_LDO_OUT: C25.1 C26.1 C35.1 U5.A2(DIG_LDO_OUT_1) U5.A3(DIG_LDO_OUT_2) U5.B15(DIG_LDO_OUT_3) U5.B26(DIG_LDO_OUT_4) U5.B27(DIG_LDO_OUT_5) U5.B35(DIG_LDO_OUT_6) U5.B36(DIG_LDO_OUT_7)
DVIO_1V8_5229: C37.1 J5.2 R12.1 S4.1(S1) U10.40(DVIO)
HCI_CTS_1V8_CC: R35.2 U10.23(P1.5)
HCI_RTS_1V8_CC: R34.2 U10.22(P1.4)
HCI_RX_1V8_CC: R27.2 U10.37(P3.3/UCA0TXD)
HCI_TX_1V8_CC: R26.2 U10.38(P3.4/UCA0RXD)
I2C_SCL_1V8_5229: J34.2 U10.35(P3.1/UCB0SCL)
I2C_SDA_1V8_5229: J36.1 U10.34(P3.0/UCB0SDA)
IOVDD_1V8_MIC: C53.1 C54.1 C55.1 C56.1 J31.2 R16.1 R17.1 U12.21(IOVDD) U12.22(DVDD)
JTAG_PWR_3V3: J2.2(1) S3.3
LED1: R6.1 U10.19(P1.1)
LED2: R7.1 U10.20(P1.2)
LED3: R15.1 U10.21(P1.3)
MLDO_OUT: C20.1 U5.A5(MLDO_OUT_1) U5.A9(MLDO_OUT_2) U5.B2(MLDO_OUT_3) U5.B7(MLDO_OUT_4)
nRST/SBWTDIO_5229: C43.1 J2.11(13) R28.2 U10.64(nRSTDVCC/SBWTDIO)
nSHUTDOWN_1V8_CC: U5.A6(nSHUTD) U10.25(P1.7)
RF_ANT: FL1.2(OUT) R29.2 R30.2
SLO: C30.1 U5.B1(SRAM_LDO_OUT)
SLOW_CLK_1V8_CC: R10.2 R11.1 R25.2
SMCLK_5229: J17.1 U10.28(P2.2)
TCK_5229: J2.7(11) U10.63(PJ.3/TCK)
TDI_5229: J2.3(9) U10.61(PJ.1/TDI)
TDO_5229: J2.1(8) U10.60(PJ.0/TDO)
TEST/SBWTCK_5229: J2.8(4) U10.59(TEST/SBWTCK)
TMS_5229: J2.5(10) U10.62(PJ.2/TMS)
UBAL5: P3.1 R30.1
USB_5V: C32.1 J4.1(VBUS) J14.1 U9.1(IN)
VCORE: C41.1 U10.17(VCORE)
VIO_1V8_CC: C17.1 J12.2 U5.A17(VDD_IO_1) U5.A34(VDD_IO_2) U5.A38(VDD_IO_3) U5.B18(VDD_IO_4) U5.B19(VDD_IO_5) U5.B21(VDD_IO_6) U5.B22(VDD_IO_7) U5.B25(VDD_IO_8)
N81643: S4.2(S2) U10.31(P2.5)
N81789: S4.A0(S0) U10.30(P2.4)
N134906: J36.2 R17.2 U12.18(SDA)
N140210: J37.1 J39.5
N140367: C60.1 R37.1
N148311: J32.1 U12.1(BCLK)
N148461: J35.1 U12.3(DOUT)
N148590: J33.1 U12.2(WCLK)
N151083: C60.2 U12.11(IN1R)
N151287: J28.1 J39.4
N151328: R19.2 U12.5(MICBIAS1)
N151337: C61.2 U12.8(IN1L)
N153645: J34.1 R16.2 U12.17(SCL)
N160490: J4.2(D-) R13.1
N163005: R20.1 U12.14(MICBIAS2)
N180634: J39.2 R19.1 R36.2
N180654: C61.1 R36.1
N180794: J39.3 R20.2 R37.2
N200636: R3.1 U9.2(ISET)
N200648: C36.1 J13.2 R4.1 R9.1 U9.12(OUT)
N200654: D1.2(CATHODE) U9.10(nCHG)
N200660: D1.1(ANODE) R4.2
N200680: R5.1 U9.4(PRETERM)
N200686: J14.2 U9.9(ISET2)
N200702: J3.1(POS) J13.1 J22.1 J26.1(+) S2.2
N200706: R14.2 U9.5(D+)
N200710: R13.2 U9.8(D-)
N200714: D4.2(CATHODE) U9.6(nPG)
N200730: R8.1 U9.11(TS)
N200762: J4.3(D+) R14.1
N200794: J16.2 S2.1
N201837: R34.1 U5.A32(HCI_RTS)
N201839: R35.1 U5.A29(HCI_CTS)
N201841: R26.1 U5.A33(HCI_TX)
N201843: R27.1 U5.A26(HCI_RX)
N202027: C22.2 U5.B4(FREFP) Y1.1
N202029: C23.2 U5.A4(FREFM) Y1.3
N202071: R25.1 U5.A25(SLOW_CLK_IN)
N202119: J18.1 U5.B24(TX_DBG)
N203803: C46.2 U10.13(P5.5/XOUT) Y2.2(OUT)
N203825: C47.2 U10.12(P5.4/XIN) Y2.1(IN)
N203855: J15.1 U10.46(P4.5/PM_UCA1RXD)
N203891: C44.1 R12.2 S1.2 U10.56(nRST/NMI)
N203905: D2.1(ANODE) R6.2
N203911: D3.1(ANODE) R7.2
N203925: R10.1 U10.18(P1.0)
N203941: J2.4(2) J6.2
N203951: J15.2 U10.45(P4.4/PM_UCA1TXD)
N203983: S4.3(S3) U10.32(P2.6)
N203997: D5.1(ANODE) R15.2
N205896: J23.1 U5.B33(AUD_OUT)
N214743: D4.1(ANODE) R9.2
N215059: TP11.1 U12.6(IN3L)
N215060: TP7.1 U12.24(MCLK)
N215061: TP8.1 U12.7(IN2L)

Not connected (* = marked no-connect by the designer): J2 6(3) 10(5) 12(6)* 13(14)* 14(7); J4 4(NC)* G1* G2* G3* G4*; J26 2(NC); S2 3* 4* 5* 6*; S3 4* 5* 6*; U5 A1(NC_1)* A13(NC_20)* A14(CLK_REQ_OUT)* A15(NC_21)* A16(NC_22)* A18(NC_4)* A19(NC_5)* A20(NC_6)* A21(NC_7)* A22(NC_8)* A23(NC_9)* A27(NC_10)* A30(NC_11)* A31(NC_12)* A36(NC_23)* A37(NC_24)* A39(NC_25)* A40(NC_13)* B12(NC_26)* B13(NC_27)* B14(NC_28)* B16(NC_16) B17(NC_17) B20(NC_18) B23(NC_19) B28(NC_32)* B29(NC_29)* B30(NC_30)* B31(NC_31)*; U9 7(NC)*; U10 4(P6.3/CB3)* 5(P6.4/CB4)* 6(P6.5/CB5)* 7(P6.6/CB6)* 8(P6.7/CB7)* 9(P5.0)* 10(P5.1)* 27(P2.1)* 29(P2.3)* 33(P2.7)* 36(P3.2)* 41(P4.0)* 42(P4.1)* 43(P4.2)* 44(P4.3)* 47(P4.6)* 48(P4.7)* 49(P7.0)* 50(P7.1)* 51(P7.2)* 52(P7.3)* 53(P7.4)* 54(P7.5)* 55(BSLEN)* 57(P5.2)* 58(P5.3)*; U12 12(IN2R)* 13(IN3R)* 19(GPIO1) 20(GPIO2)

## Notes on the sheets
sheet 1
- MSP430 RESET
- JTAG SENSE
- Label Pin 1
- 2 pos SW to select FET or LDO PWR
- CAPTOUCH SENSORS
- PREVIOUS
- VOL_UP
- NEXT
- VOL_DOWN
- DECOUPLING CAPS, AS CLOSE AS POSSIBLE TO MSP430
- MSP_ACLK_3V3
- PAUSE_PLAY
- MSP430 HOST
- ~2mA
- ~2mA
- ~2mA
sheet 2
- CC256x HCI Class 1.5 capable Bluetooth device
- TODO:
  HCI_TX_1V8_CC
- LEAVE TP
- CC256xQFN
sheet 3
- ~200mA charge current
- High - 500mA
  Low - ISET
  Float = 100mA
- 2 pos switch
- 4V2 - 3V0
- POWER SUPPLY
sheet 4
- CMA-4544PF-W
- Note: Use BCLK as clock source instead
  of MCLK
- CMA-4544PF-W
